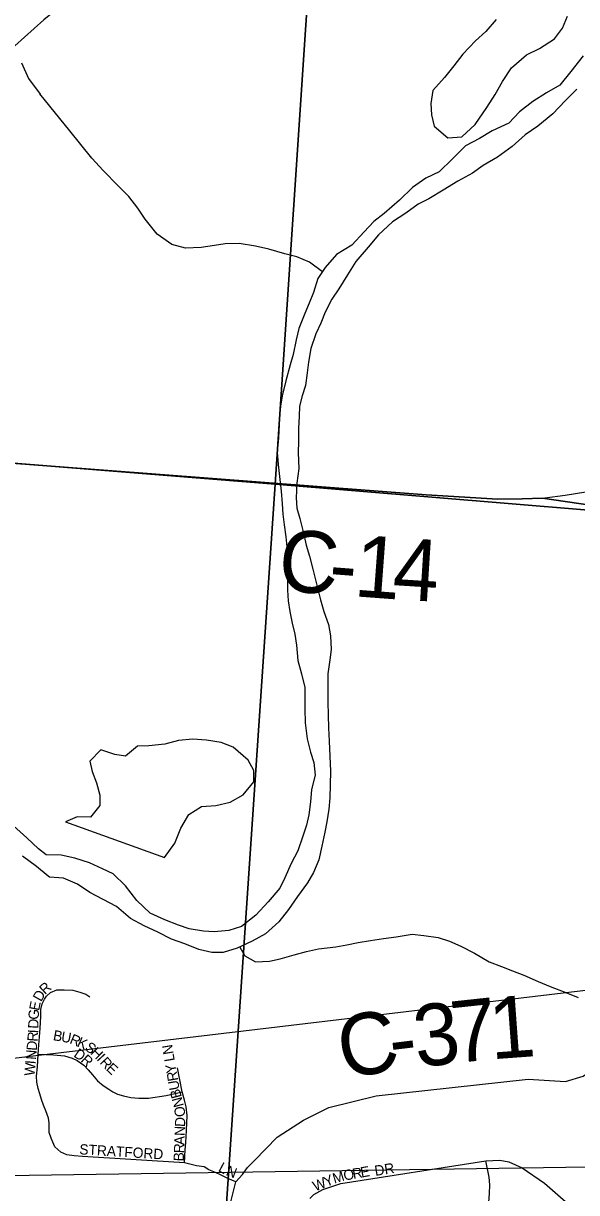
# Model space of a CAD drawing. Extents: x 0 to 34, y 0 to 22.
# Drawn here: x 7.024 to 7.534, y 17.345 to 18.421 of the extents above; entities that cross this region are included whole.
import ezdxf

# ---------------------------------------------------------------- set-up
doc = ezdxf.new("R2010")
doc.units = 0
for name, color, linetype in [('BD_P_Text', 7, 'Continuous'), ('GM_X_City_Street', 7, 'Continuous'), ('GM_X_County_Road', 7, 'Continuous'), ('GM_X_County_Road_Text', 7, 'Continuous'), ('GM_X_Interstate_Route', 7, 'Continuous'), ('GM_X_Major_River', 7, 'Continuous'), ('GM_X_Minor_Lake', 7, 'Continuous'), ('GM_X_Minor_River', 7, 'Continuous'), ('GM_X_Section', 7, 'Continuous'), ('GM_X_Township', 7, 'Continuous'), ('GM_X_Township_Subdivision', 7, 'Continuous'), ('GM_X_Township_Subdivision_Text', 7, 'Continuous')]:
    doc.layers.add(name, color=color, linetype=linetype)

msp = doc.modelspace()

# ---------------------------------------------------------------- linework, layer by layer
at = {"layer": 'BD_P_Text'}
msp.add_lwpolyline([(9.7485, 17.7931), (5.9787, 17.3454), (9.7485, 17.4014)], close=True, dxfattribs=at)
at = {"layer": 'GM_X_City_Street'}
msp.add_lwpolyline([(6.8447, 18.0301), (6.9008, 18.025), (7.2646, 17.9973)], dxfattribs=at)
at = {"layer": 'GM_X_County_Road'}
for points in [[(7.5047, 17.9845), (7.5233, 17.9868), (7.5424, 17.99), (7.5639, 17.9951), (7.6142, 18.0087), (7.6551, 18.0204)], [(7.2646, 17.9973), (7.3953, 17.9873), (7.4612, 17.9831), (7.4838, 17.9835), (7.5026, 17.9842), (7.5047, 17.9845)], [(7.2077, 17.3058), (7.2201, 17.355), (7.2261, 17.3616), (7.2307, 17.3682), (7.2373, 17.3747), (7.2581, 17.396), (7.2824, 17.4118), (7.3057, 17.4234), (7.3493, 17.4341), (7.4893, 17.4493), (7.5238, 17.4473), (7.5398, 17.4522), (7.5537, 17.4617), (7.5666, 17.4914), (7.5708, 17.5057), (7.5749, 17.5201), (7.5878, 17.597), (7.589, 17.6038)]]:
    msp.add_lwpolyline(points, dxfattribs=at)
at = {"layer": 'GM_X_Interstate_Route'}
msp.add_lwpolyline([(7.6785, 18.889), (7.5789, 18.8195), (7.5067, 18.769), (7.1647, 18.5231), (7.0432, 18.4244), (7.0075, 18.3925), (6.9382, 18.3304), (6.8835, 18.2785), (6.7808, 18.1846), (6.7503, 18.1547)], dxfattribs=at)
at = {"layer": 'GM_X_Major_River'}
for points in [[(7.54, 18.3912), (7.5286, 18.3768), (7.5184, 18.3643), (7.5062, 18.3571), (7.4937, 18.3491), (7.4812, 18.3397), (7.4714, 18.3294), (7.4562, 18.3223), (7.4445, 18.3151), (7.4316, 18.3083), (7.4191, 18.2961), (7.4074, 18.2844), (7.3949, 18.2787), (7.3828, 18.27), (7.3706, 18.2583), (7.3566, 18.2461), (7.3472, 18.2389), (7.3381, 18.2291), (7.3267, 18.217), (7.3127, 18.2083), (7.3024, 18.1965), (7.2956, 18.1863), (7.2914, 18.1734), (7.2876, 18.1635), (7.2834, 18.1541), (7.2781, 18.1404), (7.2755, 18.1298), (7.2728, 18.1165), (7.2701, 18.1067), (7.2659, 18.0922), (7.2625, 18.0782), (7.261, 18.0687), (7.2602, 18.0585), (7.2594, 18.0395), (7.2579, 18.0266), (7.259, 18.0152), (7.2605, 18.0012), (7.2616, 17.9906), (7.2627, 17.9788), (7.2634, 17.9693), (7.2645, 17.9595), (7.266, 17.9485), (7.2672, 17.9363), (7.2675, 17.9227), (7.2675, 17.8995), (7.2682, 17.8896), (7.2697, 17.8798), (7.2719, 17.8692), (7.2742, 17.8589), (7.2757, 17.8487), (7.2772, 17.8346), (7.2806, 17.8225), (7.2836, 17.81), (7.2835, 17.8001), (7.2835, 17.7902), (7.2839, 17.7773), (7.2857, 17.7625), (7.2888, 17.7504), (7.2918, 17.7409), (7.2929, 17.7291), (7.2898, 17.7159), (7.2887, 17.7045), (7.2871, 17.6927)], [(7.5342, 18.3605), (7.5233, 18.3499), (7.5119, 18.3377), (7.4982, 18.3264), (7.4865, 18.3184), (7.4744, 18.3078), (7.4611, 18.298), (7.4479, 18.2904), (7.438, 18.2832), (7.4244, 18.276), (7.4111, 18.2677), (7.3979, 18.2597), (7.388, 18.2548), (7.3767, 18.2465), (7.3642, 18.2385), (7.3513, 18.2264), (7.3418, 18.2151), (7.3304, 18.2018), (7.3229, 18.1897), (7.3149, 18.1768), (7.3084, 18.1673), (7.3024, 18.1552), (7.2982, 18.1453), (7.2936, 18.1355), (7.2891, 18.1218), (7.2868, 18.1093), (7.2856, 18.0994), (7.2841, 18.0877), (7.281, 18.0782), (7.2787, 18.0687), (7.2784, 18.0592), (7.2776, 18.0486), (7.2776, 18.0365), (7.2775, 18.0258), (7.2779, 18.0114), (7.2763, 17.9978), (7.2756, 17.9845), (7.2763, 17.975), (7.2789, 17.9655), (7.2819, 17.953), (7.2849, 17.9408), (7.2879, 17.9306), (7.291, 17.9188), (7.2943, 17.9052), (7.2981, 17.8907), (7.3011, 17.8797), (7.3052, 17.868), (7.3071, 17.8573), (7.3078, 17.8448), (7.3067, 17.8353), (7.3048, 17.8224), (7.3047, 17.7966), (7.3051, 17.7845), (7.3054, 17.7727), (7.3058, 17.7606)], [(7.3058, 17.7606), (7.3065, 17.7466), (7.3073, 17.7329), (7.3069, 17.7204), (7.3065, 17.7083), (7.3057, 17.698), (7.3038, 17.6863), (7.3019, 17.6768), (7.2992, 17.6639), (7.2965, 17.6514), (7.2916, 17.6396), (7.2859, 17.6301), (7.2768, 17.6176), (7.2684, 17.6055), (7.2597, 17.5941), (7.2472, 17.5831), (7.2351, 17.5763), (7.2211, 17.5699), (7.2082, 17.5661), (7.198, 17.5661), (7.1859, 17.5688), (7.173, 17.5741), (7.1606, 17.5783), (7.1481, 17.5848), (7.1356, 17.5905), (7.1228, 17.5974), (7.1099, 17.6084), (7.0978, 17.6149), (7.0854, 17.6213), (7.074, 17.6289), (7.0612, 17.6343), (7.0483, 17.6354)], [(7.2871, 17.6927), (7.2852, 17.6832), (7.2818, 17.673), (7.2772, 17.6597), (7.2708, 17.648), (7.2651, 17.6347), (7.2605, 17.6252), (7.2499, 17.6127), (7.2385, 17.6002), (7.2253, 17.59), (7.2135, 17.5862), (7.1999, 17.5851), (7.1901, 17.5855), (7.1769, 17.5878), (7.167, 17.5912), (7.1546, 17.5962), (7.1409, 17.6023), (7.1289, 17.6137), (7.1183, 17.6273), (7.107, 17.6384), (7.0971, 17.6429), (7.0851, 17.6486), (7.0718, 17.6528), (7.059, 17.6555), (7.0453, 17.6559)], [(7.0453, 17.6559), (7.0382, 17.6613), (7.0273, 17.6715), (7.0152, 17.6825)], [(7.0483, 17.6354), (7.0471, 17.6361), (7.0364, 17.645), (7.0235, 17.6545)]]:
    msp.add_lwpolyline(points, dxfattribs=at)
at = {"layer": 'GM_X_Minor_Lake'}
for points in [[(7.4598, 18.4246), (7.4503, 18.4136), (7.4408, 18.405), (7.429, 18.3929), (7.4209, 18.3819), (7.4122, 18.3714), (7.4015, 18.3593), (7.3996, 18.3475), (7.4003, 18.3369), (7.4028, 18.3266), (7.4152, 18.3159), (7.4281, 18.3166), (7.4403, 18.3279), (7.4513, 18.3438), (7.459, 18.3555), (7.4655, 18.3676), (7.4739, 18.3801), (7.4876, 18.3921), (7.4997, 18.3981), (7.5134, 18.4068), (7.521, 18.4166), (7.5256, 18.4276)], [(7.1544, 17.6534), (7.1639, 17.6666), (7.1693, 17.6803), (7.1766, 17.6931), (7.1884, 17.7003), (7.2016, 17.7013), (7.2148, 17.7043), (7.2266, 17.711), (7.2365, 17.7231), (7.2366, 17.7334), (7.2313, 17.7429), (7.2174, 17.7551), (7.2065, 17.7593), (7.1929, 17.7613), (7.1804, 17.7622), (7.1672, 17.7611), (7.1547, 17.7578), (7.1399, 17.7563), (7.1293, 17.756), (7.1183, 17.7466), (7.1085, 17.7482), (7.0956, 17.7524), (7.0854, 17.7422), (7.0876, 17.7327), (7.0917, 17.7221), (7.0946, 17.7107), (7.0946, 17.7012), (7.0862, 17.6906), (7.0737, 17.6907), (7.0631, 17.6862)], [(7.0631, 17.6862), (7.1544, 17.6534)]]:
    msp.add_lwpolyline(points, dxfattribs=at)
at = {"layer": 'GM_X_Minor_River'}
for points in [[(7.0224, 18.3847), (7.0291, 18.3703), (7.0396, 18.3558)], [(7.2997, 18.1925), (7.2879, 18.2013), (7.2762, 18.2063), (7.2652, 18.2091), (7.2505, 18.2133), (7.238, 18.2161), (7.2229, 18.2184), (7.2101, 18.2181), (7.2002, 18.2167), (7.1881, 18.2148), (7.1737, 18.2142), (7.1609, 18.2177), (7.1474, 18.2272), (7.1365, 18.241), (7.1297, 18.2509), (7.1215, 18.2619), (7.1117, 18.2715), (7.0978, 18.2856), (7.0873, 18.297), (7.067, 18.3222), (7.0394, 18.3561)], [(7.2235, 17.571), (7.2283, 17.563), (7.2381, 17.5573), (7.251, 17.5579), (7.2609, 17.5602), (7.2737, 17.5639), (7.2851, 17.5668), (7.2961, 17.5694), (7.312, 17.5712), (7.3222, 17.5731), (7.3328, 17.5753), (7.3441, 17.5771), (7.3559, 17.5789), (7.3676, 17.5804), (7.3824, 17.583), (7.393, 17.5817), (7.4062, 17.5798), (7.4167, 17.5763), (7.4273, 17.5717), (7.4397, 17.5655), (7.4533, 17.5575), (7.4646, 17.5532), (7.4748, 17.549), (7.4854, 17.5451), (7.4986, 17.5394), (7.5095, 17.5347), (7.5239, 17.5293), (7.5352, 17.5247)]]:
    msp.add_lwpolyline(points, dxfattribs=at)
at = {"layer": 'GM_X_Section'}
for points in [[(6.8218, 19.0519), (7.324, 19.0124), (7.2561, 17.997), (6.7511, 18.0375)], [(7.324, 19.0124), (7.832, 18.9749), (7.7594, 17.9553), (7.2561, 17.997)], [(6.2087, 18.0808), (6.2447, 18.0791), (6.7511, 18.0375), (7.2561, 17.997), (7.1918, 17.0445), (6.1439, 17.131)], [(7.2561, 17.997), (7.7594, 17.9553), (8.2612, 17.9133), (8.2873, 17.9124), (8.2155, 16.9751), (7.1918, 17.0445)]]:
    msp.add_lwpolyline(points, close=True, dxfattribs=at)
at = {"layer": 'GM_X_Township'}
for points in [[(5.5177, 18.1312), (5.8763, 18.1039), (6.0361, 18.0921), (6.6338, 18.046), (6.7247, 18.0386), (6.7448, 18.0381), (6.7612, 18.0376), (6.9008, 18.025), (7.3953, 17.9873), (7.4612, 17.9831), (7.4838, 17.9835), (7.5026, 17.9842), (7.5797, 17.9729), (7.6687, 17.9677), (7.9634, 17.9394), (7.994, 17.9365), (8.1574, 17.9293), (8.2509, 17.9206), (8.2846, 17.9178), (8.6396, 17.8902), (9.2909, 17.8381), (9.3736, 17.8315), (9.4, 17.8295)], [(9.4, 17.8295), (9.3736, 17.8315), (9.2909, 17.8381), (8.6396, 17.8902), (8.2846, 17.9178), (8.2509, 17.9206), (8.1574, 17.9293), (7.994, 17.9365), (7.9634, 17.9394), (7.6687, 17.9677), (7.5797, 17.9729), (7.5026, 17.9842), (7.4838, 17.9835), (7.4612, 17.9831), (7.3953, 17.9873), (6.9008, 18.025), (6.7612, 18.0376), (6.7448, 18.0381), (6.7247, 18.0386), (6.6338, 18.046), (6.0361, 18.0921), (5.8763, 18.1039), (5.5177, 18.1312)]]:
    msp.add_lwpolyline(points, dxfattribs=at)
at = {"layer": 'GM_X_Township_Subdivision'}
for points in [[(7.0493, 17.5292), (7.0551, 17.5315), (7.0618, 17.5315), (7.0699, 17.5313), (7.0762, 17.5296), (7.0818, 17.5277), (7.0856, 17.5252)], [(7.0532, 17.3871), (7.0514, 17.3913), (7.0497, 17.3952), (7.0481, 17.4004), (7.0481, 17.4046), (7.048, 17.4092), (7.0474, 17.4134), (7.0461, 17.4169), (7.0449, 17.4203), (7.0428, 17.4255), (7.0408, 17.4307), (7.0393, 17.4359), (7.038, 17.4407), (7.0368, 17.4466), (7.0363, 17.4522), (7.0372, 17.4608), (7.0378, 17.4725), (7.0386, 17.481), (7.0395, 17.4921), (7.0401, 17.5012), (7.0403, 17.5077), (7.0403, 17.5134), (7.0416, 17.5188), (7.0436, 17.523), (7.0457, 17.5257), (7.0493, 17.5292)], [(7.0378, 17.4725), (7.052, 17.4718), (7.0622, 17.471), (7.0691, 17.4687), (7.0739, 17.4666), (7.08, 17.4622), (7.0839, 17.4581), (7.0879, 17.4535), (7.0925, 17.448), (7.0979, 17.4437), (7.1029, 17.4403), (7.1067, 17.4378), (7.111, 17.4357), (7.1165, 17.4341), (7.1231, 17.4326), (7.1307, 17.4318), (7.1396, 17.432), (7.1557, 17.4343), (7.1705, 17.4376)], [(7.1726, 17.3723), (7.1732, 17.3844), (7.1739, 17.3911), (7.1743, 17.3965), (7.1745, 17.4023), (7.1751, 17.4159), (7.1743, 17.4238), (7.1728, 17.4301), (7.1705, 17.4376), (7.1663, 17.4599)], [(7.2201, 17.355), (7.2125, 17.358), (7.2064, 17.3611), (7.2013, 17.3636), (7.1952, 17.3661), (7.1907, 17.3687), (7.1836, 17.3697), (7.1726, 17.3723), (7.0786, 17.3783), (7.071, 17.3788), (7.0644, 17.3798), (7.0589, 17.3821), (7.0532, 17.3871)], [(7.288, 17.3397), (7.2918, 17.3434), (7.3002, 17.3479), (7.3166, 17.3533), (7.4503, 17.3742), (7.4633, 17.3749), (7.4716, 17.3732), (7.4836, 17.3677), (7.5042, 17.3537), (7.5191, 17.3409), (7.533, 17.3289), (7.5383, 17.3243), (7.5492, 17.3184), (7.5636, 17.3114)], [(7.4402, 17.1881), (7.4499, 17.2965), (7.4518, 17.3207), (7.4537, 17.3443), (7.4538, 17.3522), (7.4532, 17.3591), (7.4503, 17.3742)]]:
    msp.add_lwpolyline(points, dxfattribs=at)

# ---------------------------------------------------------------- texts
at = {"layer": 'GM_X_County_Road_Text'}
for s, rotation, p in [('C', 355.6049, (7.2579, 17.8993)), ('1', 355.7488, (7.3279, 17.8939)), ('4', 356.3805, (7.3634, 17.8913)), ('-', 355.6286, (7.3045, 17.8957)), ('3', 6.246, (7.3867, 17.4602)), ('7', 6.1203, (7.4212, 17.464)), ('1', 4.1918, (7.4552, 17.4676)), ('C', 10.1897, (7.3192, 17.4493)), ('-', 6.9621, (7.364, 17.4574))]:
    msp.add_text(s, height=0.0568, rotation=rotation, dxfattribs=at).set_placement(p)
at = {"layer": 'GM_X_Township_Subdivision_Text'}
for s, rotation, p in [('D', 60.6482, (7.0406, 17.5201)), ('R', 42.5955, (7.0442, 17.5267)), ('E', 78.8937, (7.0387, 17.5119)), ('G', 87.5076, (7.0383, 17.504)), ('D', 87.6284, (7.038, 17.4957)), ('R', 85.5326, (7.0372, 17.4837)), ('I', 86.8649, (7.0378, 17.4914)), ('B', 349.8429, (7.0511, 17.4854)), ('U', 349.8477, (7.0585, 17.4841)), ('R', 337.2288, (7.0662, 17.4827)), ('K', 336.3681, (7.073, 17.4799)), ('N', 85.2739, (7.0358, 17.467)), ('D', 85.2509, (7.0365, 17.4753)), ('D', 326.1038, (7.0699, 17.4706)), ('S', 324.6275, (7.0802, 17.4768)), ('H', 316.113, (7.0854, 17.4731)), ('N', 99.637, (7.1627, 17.4729)), ('I', 85.2672, (7.0354, 17.4629)), ('R', 316.9063, (7.0765, 17.4662)), ('I', 312.7119, (7.0913, 17.4675)), ('R', 312.7195, (7.0941, 17.4644)), ('L', 99.633, (7.1638, 17.4664)), ('W', 85.2531, (7.0345, 17.4521)), ('E', 317.3347, (7.0998, 17.4583)), ('Y', 99.637, (7.1656, 17.4557)), ('R', 99.638, (7.1669, 17.4483)), ('U', 100.1524, (7.1683, 17.4401)), ('B', 104.2306, (7.1702, 17.433)), ('N', 105.1873, (7.1723, 17.425)), ('O', 95.7887, (7.1735, 17.4151)), ('D', 87.8797, (7.1732, 17.4053)), ('N', 87.8874, (7.1729, 17.397)), ('STRATFORD', 356.467, (7.0756, 17.3803)), ('R', 87.891, (7.1723, 17.3811)), ('A', 87.8579, (7.1726, 17.3886)), ('B', 87.8627, (7.172, 17.3736)), ('L', 331.6752, (7.2031, 17.3651)), ('N', 339.246, (7.2102, 17.3613)), ('E', 10.0219, (7.3356, 17.3588)), ('DR', 8.9673, (7.3485, 17.3603)), ('W', 22.0418, (7.2931, 17.346)), ('Y', 22.0449, (7.3032, 17.3501)), ('M', 16.7934, (7.3107, 17.3532)), ('O', 10.2638, (7.32, 17.356)), ('R', 10.0094, (7.3282, 17.3575))]:
    msp.add_text(s, height=0.00947, rotation=rotation, dxfattribs=at).set_placement(p)

doc.saveas('drawing.dxf')
